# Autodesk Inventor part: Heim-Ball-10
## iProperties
Shininess: 0.0
Length Units: 11269
Angle Units: 11279
Time Units: 11290
Mass Units: 11283
Length Display Precision: 3
Angle Display Precision: 1
Compacted: True
Created: 1999-06
Part Number: Heim-Ball-10
Document SubType Name: Modeling
Designer: Administrator
Density: 1 g/cm^3
PropertySet Name: Model Information
Density: 0.0
Volumn: 0.0
Area: 0.0
Control State: 0
Master: False
Checked Out: False
Author: Administrator
